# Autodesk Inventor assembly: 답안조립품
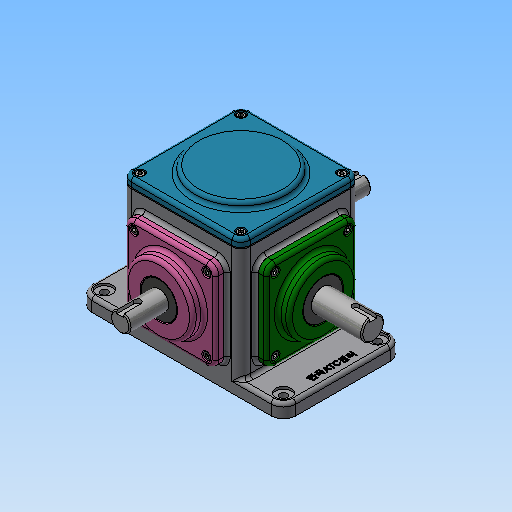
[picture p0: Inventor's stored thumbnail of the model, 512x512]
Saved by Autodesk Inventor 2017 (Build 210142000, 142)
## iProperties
Part Number: 답안조립품
Material: 일반
Document SubType Name: Assembly
Designer: MRC
Author: MRC
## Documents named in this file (16)
- C:\Users\MRC\Desktop\620307V1014\답안조립품.iam
- C:\Users\MRC\Desktop\620307V1014\본체.ipt
- C:\Users\MRC\Desktop\620307V1014\개스킷.ipt
- C:\Users\MRC\Desktop\620307V1014\메인베벨기어.ipt
- C:\Users\MRC\Desktop\620307V1014\메인축.ipt
- C:\Users\MRC\Desktop\620307V1014\메인커버.ipt
- C:\Users\MRC\Desktop\620307V1014\베어링 6203.ipt
- C:\Users\MRC\Desktop\620307V1014\베어링 6204.ipt
- C:\Users\MRC\Desktop\620307V1014\볼트 M4.ipt
- C:\Users\MRC\Desktop\620307V1014\상부커버.ipt
- C:\Users\MRC\Desktop\620307V1014\서브베벨기어.ipt
- C:\Users\MRC\Desktop\620307V1014\서브축.ipt
- C:\Users\MRC\Desktop\620307V1014\서브커버.ipt
- C:\Users\MRC\Desktop\620307V1014\오일 실 17 32 8.ipt
- C:\Users\MRC\Desktop\620307V1014\오일 실 20 35 8.ipt
- C:\Users\MRC\Desktop\620307V1014\키 4x4.ipt
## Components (1 placed, 1 different names)
1. 개스킷:1
